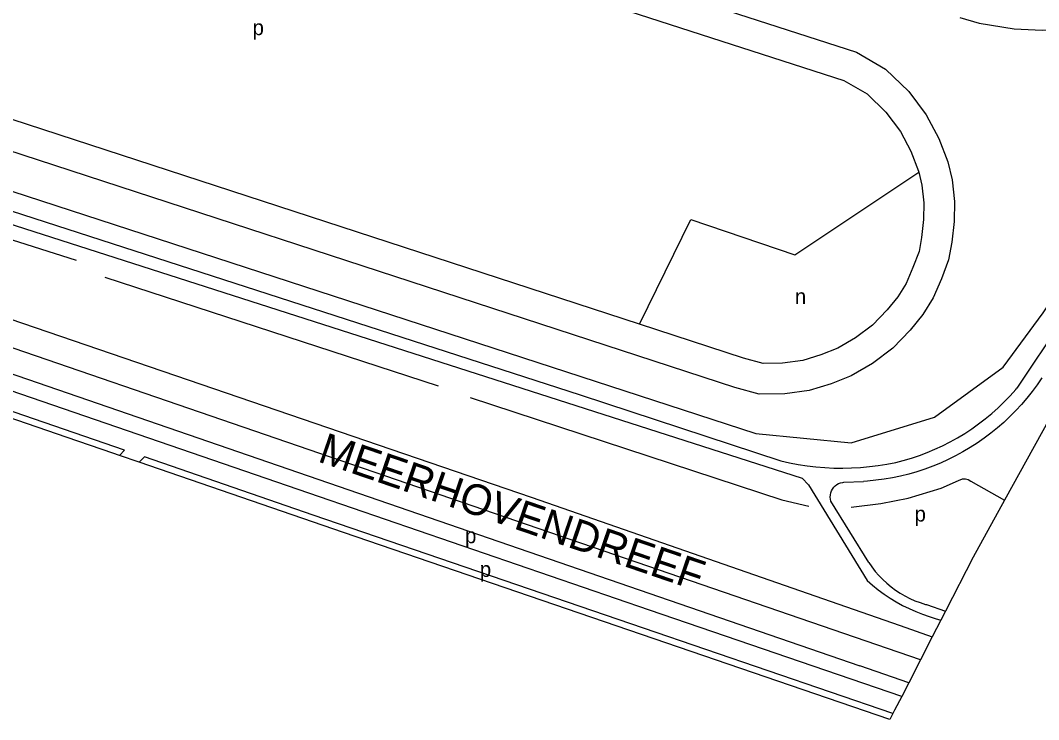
# Model space of a CAD drawing. Extents: x 154320 to 156262, y 382651 to 384180.
# Drawn here: x 155718.2 to 155984.2, y 382651.2 to 382833.8 of the extents above; entities that cross this region are included whole.
import ezdxf

# ---------------------------------------------------------------- set-up
doc = ezdxf.new("R2010")
doc.units = 0
for name, color, linetype in [('BLT_Basislijn', 7, 'Continuous'), ('BLT_Centroide', 7, 'Continuous'), ('BLT_Gemeentegrens', 7, 'Continuous'), ('BLT_Straatnaam_hoofdweg', 7, 'Continuous')]:
    doc.layers.add(name, color=color, linetype=linetype)

msp = doc.modelspace()

# ---------------------------------------------------------------- linework, layer by layer
at = {"layer": 'BLT_Basislijn'}
for p, q in [((155607.07, 382810.69), (155732.73, 382771.2)), ((155659.76, 382798.56), (155922.4, 382714.29)), ((155628.37, 382771.61), (155937.44, 382665.23)), ((155999.49, 382769.38), (155978.5, 382737.73)), ((155740.23, 382766.75), (155827.33, 382738.33)), ((155745.36, 382721.59), (155744.04, 382720.22)), ((155750.57, 382719.8), (155749.25, 382718.42)), ((155933.29, 382713.2), (155938.46, 382713.42)), ((155939.81, 382692.27), (155929.92, 382708.25)), ((155954.88, 382681.25), (155959.83, 382679.57)), ((155957.13, 382677.65), (155958.59, 382677.15)), ((155959.83, 382679.57), (155959.83, 382679.57)), ((155948.03, 382675.83), (155956.4, 382672.87)), ((155956.4, 382672.88), (155956.4, 382672.87)), ((155950.24, 382660.85), (155937.44, 382665.23))]:
    msp.add_line(p, q, dxfattribs=at)
for points in [[(155632.33, 382923.49), (155936.55, 382825.44), (155944.19, 382821.01), (155950.23, 382815.18), (155954.83, 382809.12), (155958.09, 382802.95), (155960.42, 382796.84), (155961.6, 382792.12), (155962.18, 382786.48), (155962.13, 382781.31), (155961.51, 382775.88), (155960.66, 382771.27), (155958.77, 382766.3), (155956.65, 382761.34), (155953.92, 382757), (155950.64, 382752.88), (155946.07, 382748.21), (155940.74, 382744.19), (155935.19, 382740.99), (155929.95, 382738.91), (155924.25, 382737.14), (155917.84, 382736.3), (155911.19, 382736.19), (155904.79, 382737.95), (155663.58, 382816.59)], [(155657.74, 382906.9), (155933.28, 382818.09), (155939.34, 382814.58), (155944.23, 382809.86), (155948.06, 382804.8), (155950.79, 382799.64), (155952.77, 382794.44), (155952.85, 382794.13)], [(155879.92, 382754.47), (155666.53, 382824.04), (155663.74, 382825.35), (155661.67, 382827.07), (155660.51, 382828.82), (155659.85, 382830.96), (155651.25, 382901.53)], [(155577.78, 382834.26), (155666.41, 382805.25), (155910.27, 382725.89), (155935.24, 382723.45), (155956.97, 382730.17), (155974.93, 382743.23), (155985.37, 382757.44), (156061.48, 382871.71)], [(155963.55, 382834.52), (155968.66, 382833.02), (155977.76, 382831.58), (155985.11, 382831.25), (155991.21, 382831.55), (155997.5, 382832.38), (156002.4, 382833.47), (156007.5, 382834.91), (156014.06, 382837.36), (156021.99, 382841.41), (156027.28, 382844.66), (156032.64, 382848.52), (156036.94, 382852.27), (156041.17, 382856.61), (156044.91, 382861.04), (156048.35, 382865.9), (156053.37, 382873.82)], [(155948.42, 382657.28), (155882.54, 382679.83), (155796.3, 382709.35), (155620.98, 382769.65), (155540.38, 382797.4), (155532.14, 382800.46), (155523.11, 382804.65), (155513.94, 382809.54), (155508.52, 382813.15), (155501.43, 382818.72), (155495.6, 382824.35), (155490.07, 382829.62)], [(155953.32, 382666.86), (155533.99, 382810.75), (155524.14, 382815.11)], [(155660.5, 382801.9), (155864.45, 382736.03), (155916.83, 382718.75)], [(155879.92, 382754.47), (155893.29, 382781.77), (155920.52, 382772.58), (155952.85, 382794.13)], [(155952.85, 382794.13), (155953.7, 382790.73), (155954.18, 382786.11), (155954.13, 382781.8), (155953.6, 382777.06), (155952.92, 382773.43), (155951.35, 382769.29), (155949.54, 382765.06), (155947.39, 382761.64), (155944.63, 382758.18), (155940.77, 382754.23), (155936.32, 382750.87), (155931.71, 382748.22), (155927.28, 382746.46), (155922.53, 382744.98), (155917.25, 382744.29), (155912.2, 382744.21), (155907.1, 382745.61), (155879.92, 382754.47)], [(155658.83, 382775.14), (155851.64, 382709.27), (155948.03, 382675.83)], [(155745.36, 382721.59), (155619.35, 382764.92), (155604.35, 382770.08)], [(155984.99, 382740.46), (155983.76, 382738.65), (155982.46, 382736.88), (155981.09, 382735.16), (155979.67, 382733.5), (155978.18, 382731.89), (155976.64, 382730.33), (155975.04, 382728.83), (155973.39, 382727.39), (155971.68, 382726.01), (155969.93, 382724.69), (155968.13, 382723.44), (155966.29, 382722.26), (155964.4, 382721.14), (155962.47, 382720.09), (155960.51, 382719.12), (155958.52, 382718.21), (155956.49, 382717.38), (155954.43, 382716.62), (155952.34, 382715.95), (155950.24, 382715.34), (155948.11, 382714.81), (155945.96, 382714.37), (155943.8, 382714), (155941.63, 382713.71), (155939.45, 382713.49), (155938.46, 382713.42)], [(155948.81, 382718.83), (155950.92, 382719.46), (155953.01, 382720.16), (155955.06, 382720.95), (155957.09, 382721.8), (155959.09, 382722.74), (155961.05, 382723.74), (155962.98, 382724.81), (155964.86, 382725.95), (155966.7, 382727.16), (155968.5, 382728.44), (155970.24, 382729.78), (155971.94, 382731.18), (155973.59, 382732.64), (155975.18, 382734.17), (155976.72, 382735.74), (155978.2, 382737.38), (155978.5, 382737.73)], [(155835.71, 382735.3), (155917.06, 382708.61), (155924.18, 382706.91)], [(155946.11, 382652.78), (155880.92, 382675.1), (155794.68, 382704.63), (155750.57, 382719.8)], [(155916.83, 382718.75), (155919.1, 382718.24), (155921.39, 382717.82), (155923.69, 382717.47), (155926, 382717.2), (155928.32, 382717.01), (155930.65, 382716.9), (155932.98, 382716.87), (155935.3, 382716.92), (155937.63, 382717.05), (155939.95, 382717.27), (155942.26, 382717.55), (155944.55, 382717.92), (155946.84, 382718.37), (155948.81, 382718.83)], [(155922.4, 382714.29), (155924.07, 382712.52), (155939.36, 382687.55)], [(155929.92, 382708.25), (155929.78, 382708.78), (155929.73, 382709.33), (155929.76, 382709.88), (155929.86, 382710.42), (155930.05, 382710.94), (155930.3, 382711.42), (155930.63, 382711.87), (155931.01, 382712.26), (155931.45, 382712.59), (155931.93, 382712.86), (155932.45, 382713.05), (155932.99, 382713.17), (155933.29, 382713.2)], [(155935.16, 382706.67), (155942.99, 382707.62), (155950.12, 382709.05), (155958.72, 382711.61), (155963.24, 382713.68), (155964.32, 382714.05), (155965.06, 382714.08), (155965.77, 382713.87), (155966.42, 382713.51), (155975.24, 382708.49)], [(155939.81, 382692.27), (155940.63, 382691.08), (155941.51, 382689.93), (155942.46, 382688.84), (155943.46, 382687.8), (155944.52, 382686.82), (155945.64, 382685.89), (155946.8, 382685.03), (155948.01, 382684.24), (155949.26, 382683.51), (155950.55, 382682.85), (155951.87, 382682.27), (155953.22, 382681.76), (155954.6, 382681.32), (155954.88, 382681.25)], [(155939.36, 382687.55), (155940.79, 382686.3), (155942.27, 382685.12), (155943.79, 382684.01), (155945.36, 382682.96), (155946.98, 382681.97), (155948.63, 382681.05), (155950.33, 382680.21), (155952.05, 382679.44), (155953.81, 382678.74), (155955.6, 382678.12), (155957.13, 382677.65)]]:
    msp.add_lwpolyline(points, dxfattribs=at)
at = {"layer": 'BLT_Gemeentegrens'}
for points in [[(156033.18, 382800.91), (155998.46, 382750.52), (155975.24, 382708.49)], [(155744.04, 382720.22), (155742.3, 382720.81), (155730.39, 382724.91), (155701.48, 382734.84), (155637.36, 382756.88), (155620.4, 382762.71), (155604.23, 382768.27)], [(155749.25, 382718.42), (155744.04, 382720.22)], [(155946.11, 382652.78), (155945.31, 382651.22), (155802.6, 382700.09), (155749.25, 382718.42)], [(155975.24, 382708.49), (155967.04, 382693.66), (155959.83, 382679.57)], [(155959.83, 382679.57), (155958.59, 382677.15)], [(155958.59, 382677.15), (155956.4, 382672.87)], [(155956.4, 382672.87), (155953.32, 382666.86)], [(155953.32, 382666.86), (155950.24, 382660.85)], [(155950.24, 382660.85), (155948.42, 382657.28)], [(155948.42, 382657.28), (155946.56, 382653.66), (155946.11, 382652.78)]]:
    msp.add_lwpolyline(points, dxfattribs=at)

# ---------------------------------------------------------------- texts
at = {"layer": 'BLT_Centroide'}
for s, p in [('p', (155778.82, 382829.92)), ('n', (155920.48, 382759.71)), ('p', (155951.75, 382702.94)), ('p', (155834.32, 382697.28)), ('p', (155838.19, 382688.48))]:
    msp.add_text(s, height=4, dxfattribs=at).set_placement(p)
at = {"layer": 'BLT_Straatnaam_hoofdweg'}
msp.add_text('MEERHOVENDREEF', height=8, rotation=341.1394, dxfattribs=at).set_placement((155795.58, 382718.69))

doc.saveas('drawing.dxf')
